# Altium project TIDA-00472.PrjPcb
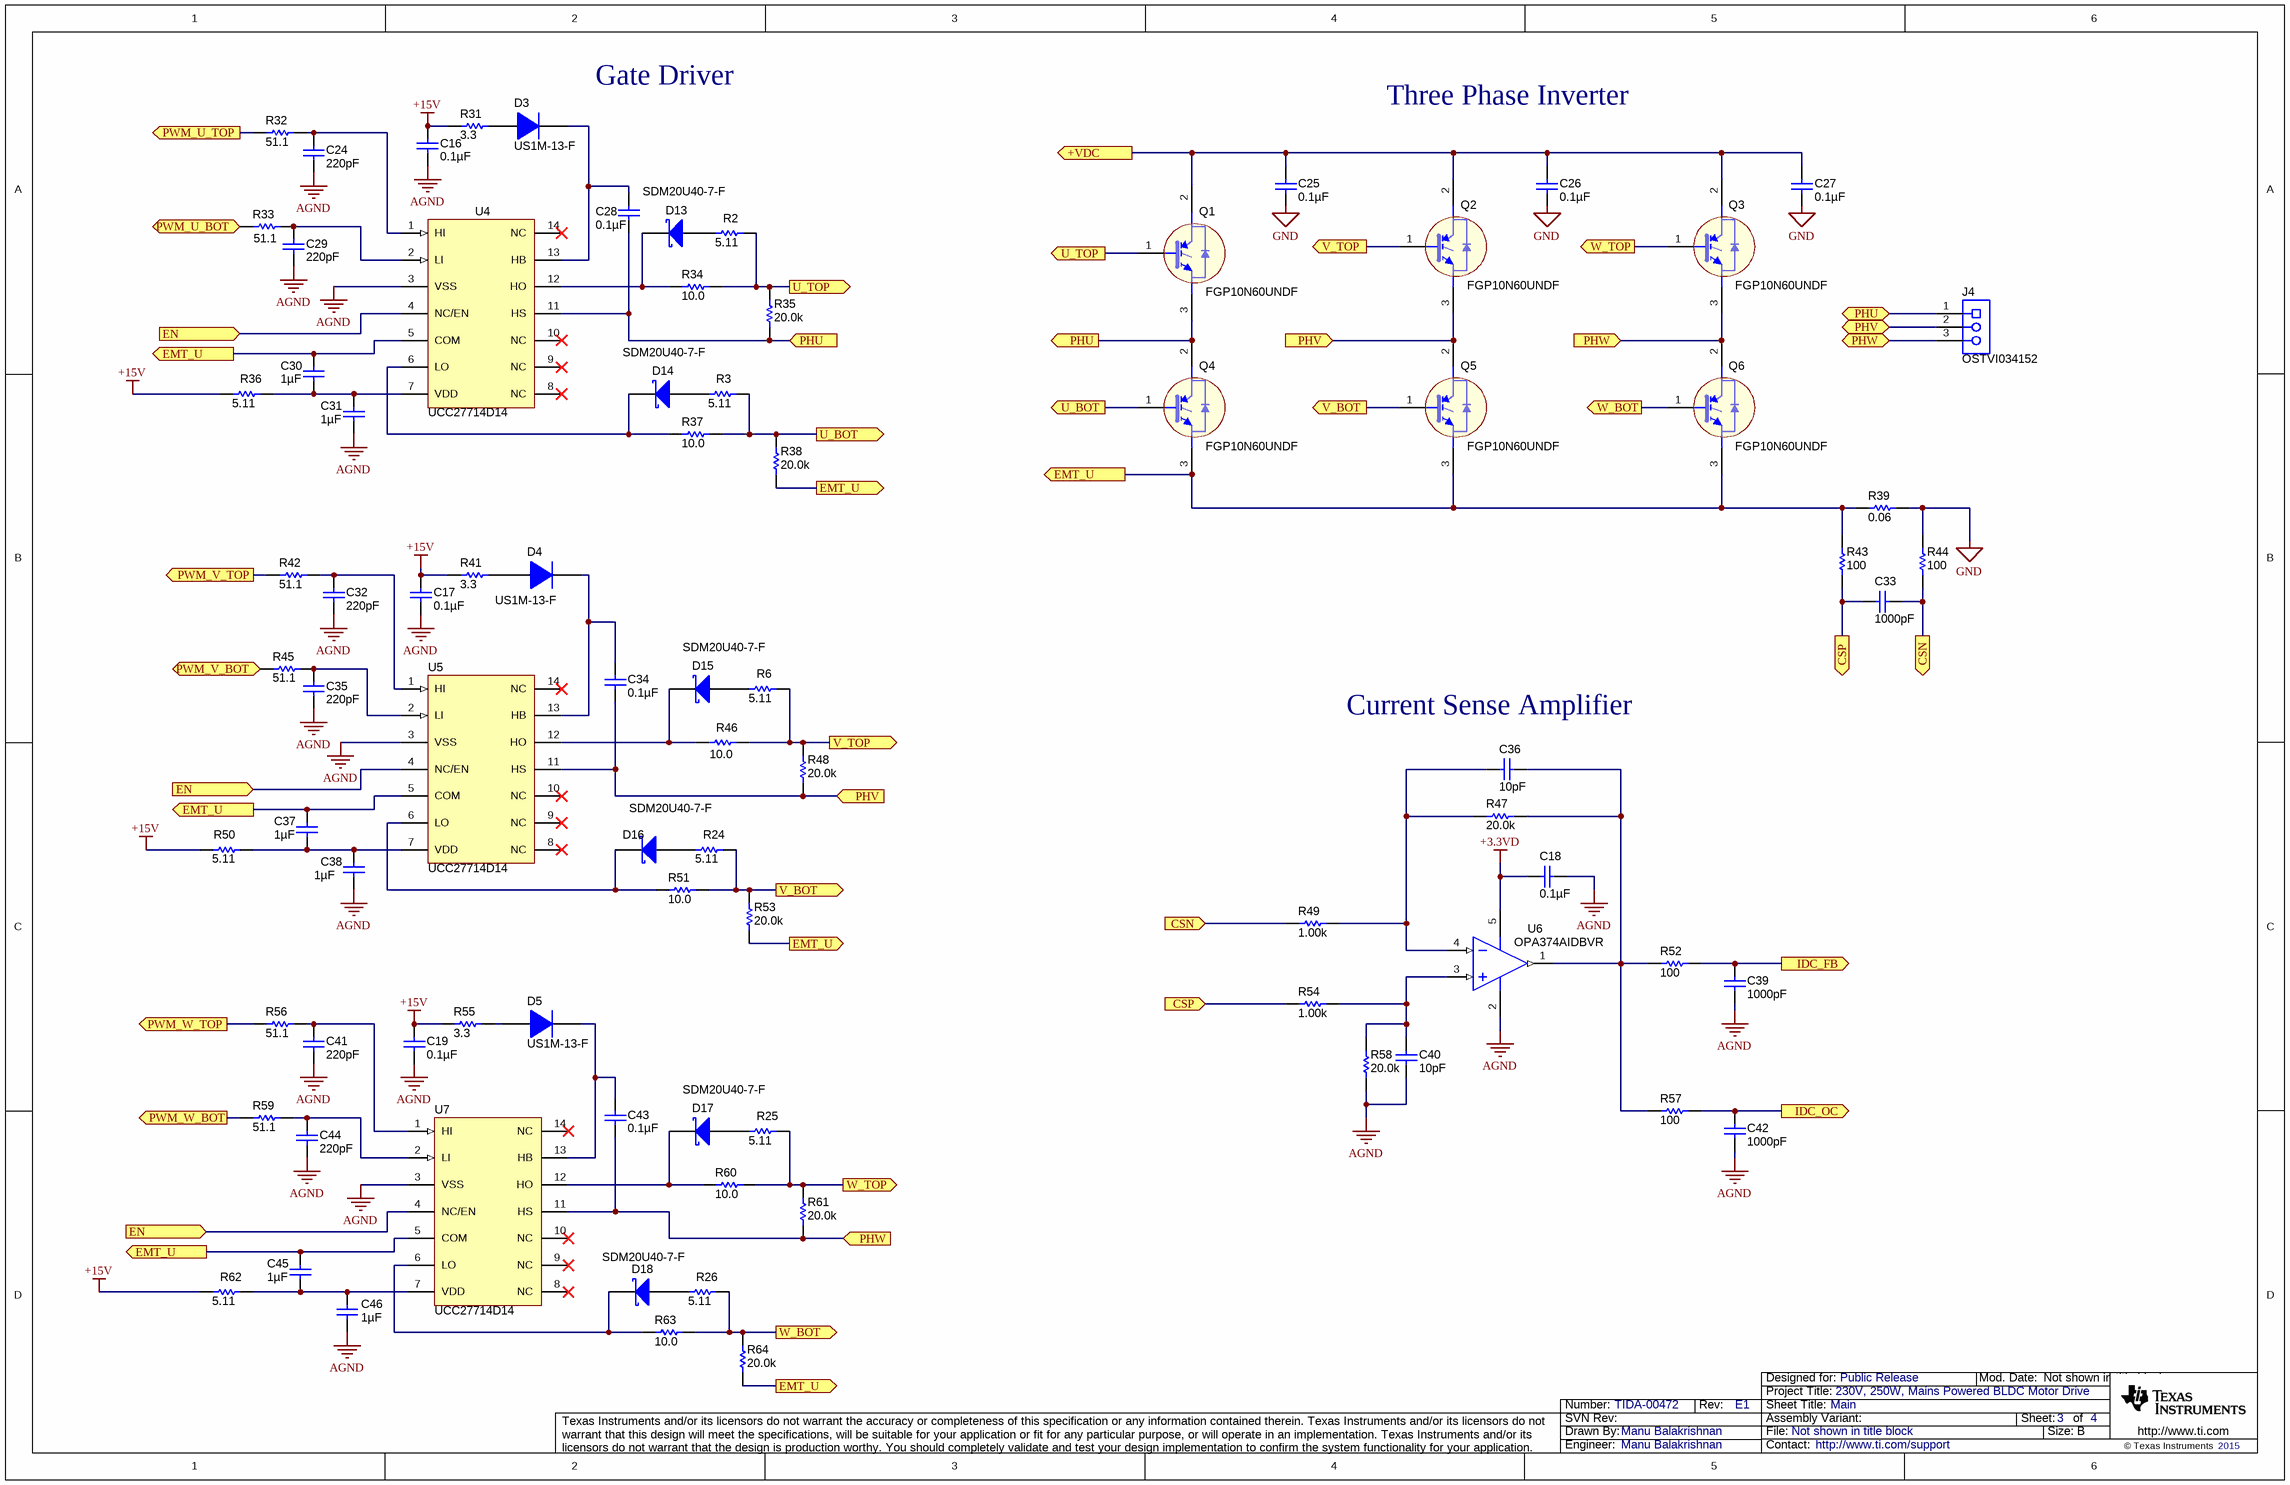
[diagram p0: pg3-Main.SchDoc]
CopyrightYear: 2015; PCB_Layout: Avinash N; PCB_Rev: E1; PRJ_Customer: Public Release; PRJ_Engineer: Manu Balakrishnan; PRJ_Number: TIDA-00472; PRJ_Title: 230V, 250W, Mains Powered BLDC Motor Drive; SCH_Rev: E1; TechSupport: http://www.ti.com/support
4 sheets, 187 parts. Net scope: flat (ports and power ports of the same name join across sheets).
Board file: TIDA-00472.PcbDoc
Sheets:
  pg3-Main.SchDoc
  Pg4-Hardware.SchDoc
  Pg1-Cover_1.SchDoc
  Pg2-Main_1.SchDoc

## Sheet pg3-Main.SchDoc: Main
size 431 x 279 mm; Date: Not shown in title block; ApprovedBy: Not shown in title block; CheckedBy: Not shown in title block; Author: Not shown in title block; CompanyName: Not shown in title block; DrawnBy: Manu Balakrishnan; Engineer: Not shown in title block; Organization: Not shown in title block; Address1: Not shown in title block; Address2: Not shown in title block; Address3: Not shown in title block; Address4: Not shown in title block; DocumentNumber: 2; Revision: Use project parameter SCH_Rev; SheetNumber: 3; SheetTotal: 4; PageSetup: Record=PageOptions¦CenterHorizontal=True¦CenterVertical=True¦PrintScale=0.64¦XCorrection=1.00¦YCorrection=1.00¦PrintKind=0¦BorderSize=5000000¦LeftOffset=0¦BottomOffset=0¦Orientation=2¦PaperLength=1000¦PaperWidth=1000¦Scale=100¦PaperSource=15¦PrintQuality=600¦MediaType=1¦DitherType=10¦PrintScaleMode=1¦PaperKind=Letter

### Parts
C16  ValueDisplayed: 0.1µF  [0603]  (hidden comment: 06033C104JAT2A)
C17  ValueDisplayed: 0.1µF  [0603]  (hidden comment: 06033C104JAT2A)
C18  ValueDisplayed: 0.1µF  [0603]  (hidden comment: 0603YC104JAT2A)
C19  ValueDisplayed: 0.1µF  [0603]  (hidden comment: 06033C104JAT2A)
C24  ValueDisplayed: 220pF  [0603]  (hidden comment: 06035A221FAT2A)
C25  ValueDisplayed: 0.1µF  [1812]  (hidden comment: C1812V104KDRACTU)
C26  ValueDisplayed: 0.1µF  [1812]  (hidden comment: C1812V104KDRACTU)
C27  ValueDisplayed: 0.1µF  [1812]  (hidden comment: C1812V104KDRACTU)
C28  ValueDisplayed: 0.1µF  [0805_HV]  (hidden comment: GRM21BR71E104KA01L)
C29  ValueDisplayed: 220pF  [0603]  (hidden comment: 06035A221FAT2A)
C30  ValueDisplayed: 1µF  [0805_HV]  (hidden comment: GRM21BR71E105KA99L)
C31  ValueDisplayed: 1µF  [0805_HV]  (hidden comment: GRM21BR71E105KA99L)
C32  ValueDisplayed: 220pF  [0603]  (hidden comment: 06035A221FAT2A)
C33  ValueDisplayed: 1000pF  [0603]  (hidden comment: GRM188R61H102KA01D)
C34  ValueDisplayed: 0.1µF  [0805_HV]  (hidden comment: GRM21BR71E104KA01L)
C35  ValueDisplayed: 220pF  [0603]  (hidden comment: 06035A221FAT2A)
C36  ValueDisplayed: 10pF  [0603]  (hidden comment: 06035A100JAT2A)
C37  ValueDisplayed: 1µF  [0805_HV]  (hidden comment: GRM21BR71E105KA99L)
C38  ValueDisplayed: 1µF  [0805_HV]  (hidden comment: GRM21BR71E105KA99L)
C39  ValueDisplayed: 1000pF  [0603]  (hidden comment: GRM188R61H102KA01D)
C40  ValueDisplayed: 10pF  [0603]  (hidden comment: 06035A100JAT2A)
C41  ValueDisplayed: 220pF  [0603]  (hidden comment: 06035A221FAT2A)
C42  ValueDisplayed: 1000pF  [0603]  (hidden comment: GRM188R61H102KA01D)
C43  ValueDisplayed: 0.1µF  [0805_HV]  (hidden comment: GRM21BR71E104KA01L)
C44  ValueDisplayed: 220pF  [0603]  (hidden comment: 06035A221FAT2A)
C45  ValueDisplayed: 1µF  [0805_HV]  (hidden comment: GRM21BR71E105KA99L)
C46  ValueDisplayed: 1µF  [0805_HV]  (hidden comment: GRM21BR71E105KA99L)
D3  US1M-13-F  [SMA]
D4  US1M-13-F  [SMA]
D5  US1M-13-F  [SMA]
D13  SDM20U40-7-F  [SOD-523]
D14  SDM20U40-7-F  [SOD-523]
D15  SDM20U40-7-F  [SOD-523]
D16  SDM20U40-7-F  [SOD-523]
D17  SDM20U40-7-F  [SOD-523]
D18  SDM20U40-7-F  [SOD-523]
J4  OSTVI034152  [ONSHORE_OSTVI034152]
Q1  FGP10N60UNDF  [TO-220AB]
Q2  FGP10N60UNDF  [TO-220AB]
Q3  FGP10N60UNDF  [TO-220AB]
Q4  FGP10N60UNDF  [TO-220AB]
Q5  FGP10N60UNDF  [TO-220AB]
Q6  FGP10N60UNDF  [TO-220AB]
R2  ValueDisplayed: 5.11  [0603]  (hidden comment: RC0603FR-075R11L)
R3  ValueDisplayed: 5.11  [0603]  (hidden comment: RC0603FR-075R11L)
R6  ValueDisplayed: 5.11  [0603]  (hidden comment: RC0603FR-075R11L)
R24  ValueDisplayed: 5.11  [0603]  (hidden comment: RC0603FR-075R11L)
R25  ValueDisplayed: 5.11  [0603]  (hidden comment: RC0603FR-075R11L)
R26  ValueDisplayed: 5.11  [0603]  (hidden comment: RC0603FR-075R11L)
R31  ValueDisplayed: 3.3  [0603]  (hidden comment: CRCW06033R30JNEA)
R32  ValueDisplayed: 51.1  [0603]  (hidden comment: CRCW060351R1FKEA)
R33  ValueDisplayed: 51.1  [0603]  (hidden comment: CRCW060351R1FKEA)
R34  ValueDisplayed: 10.0  [0603]  (hidden comment: CRCW060310R0FKEAHP)
R35  value 20.0k  [0603]  (hidden comment: CRCW060320K0FKEA)
R36  ValueDisplayed: 5.11  [0603]  (hidden comment: RC0603FR-075R11L)
R37  ValueDisplayed: 10.0  [0603]  (hidden comment: CRCW060310R0FKEAHP)
R38  value 20.0k  [0603]  (hidden comment: CRCW060320K0FKEA)
R39  ValueDisplayed: 0.06  [2512]  (hidden comment: PE2512FKE7W0R06L)
R41  ValueDisplayed: 3.3  [0603]  (hidden comment: CRCW06033R30JNEA)
R42  ValueDisplayed: 51.1  [0603]  (hidden comment: CRCW060351R1FKEA)
R43  ValueDisplayed: 100  [0603]  (hidden comment: CRCW0603100RFKEA)
R44  ValueDisplayed: 100  [0603]  (hidden comment: CRCW0603100RFKEA)
R45  ValueDisplayed: 51.1  [0603]  (hidden comment: CRCW060351R1FKEA)
R46  ValueDisplayed: 10.0  [0603]  (hidden comment: CRCW060310R0FKEAHP)
R47  ValueDisplayed: 20.0k  [0603]  (hidden comment: RG1608P-203-B-T5)
R48  value 20.0k  [0603]  (hidden comment: CRCW060320K0FKEA)
R49  ValueDisplayed: 1.00k  [0603]  (hidden comment: CRCW06031K00FKEA)
R50  ValueDisplayed: 5.11  [0603]  (hidden comment: RC0603FR-075R11L)
R51  ValueDisplayed: 10.0  [0603]  (hidden comment: CRCW060310R0FKEAHP)
R52  ValueDisplayed: 100  [0603]  (hidden comment: CRCW0603100RFKEA)
R53  value 20.0k  [0603]  (hidden comment: CRCW060320K0FKEA)
R54  ValueDisplayed: 1.00k  [0603]  (hidden comment: CRCW06031K00FKEA)
R55  ValueDisplayed: 3.3  [0603]  (hidden comment: CRCW06033R30JNEA)
R56  ValueDisplayed: 51.1  [0603]  (hidden comment: CRCW060351R1FKEA)
R57  ValueDisplayed: 100  [0603]  (hidden comment: CRCW0603100RFKEA)
R58  ValueDisplayed: 20.0k  [0603]  (hidden comment: RG1608P-203-B-T5)
R59  ValueDisplayed: 51.1  [0603]  (hidden comment: CRCW060351R1FKEA)
R60  ValueDisplayed: 10.0  [0603]  (hidden comment: CRCW060310R0FKEAHP)
R61  value 20.0k  [0603]  (hidden comment: CRCW060320K0FKEA)
R62  ValueDisplayed: 5.11  [0603]  (hidden comment: RC0603FR-075R11L)
R63  ValueDisplayed: 10.0  [0603]  (hidden comment: CRCW060310R0FKEAHP)
R64  value 20.0k  [0603]  (hidden comment: CRCW060320K0FKEA)
U4  UCC27714D14  [D0014A_N]
U5  UCC27714D14  [D0014A_N]
U6  OPA374AIDBVR  [DBV0005A_N]
U7  UCC27714D14  [D0014A_N]

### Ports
+VDC (out), CSN (in), CSN (out), CSP (in), CSP (out), EMT_U (out), EN (in), IDC_FB (out), IDC_OC (out), PHU (bidir), PHU (in), PHU (out), PHV (bidir), PHV (in), PHW (bidir), PHW (in), PWM_U_BOT (out), PWM_U_TOP (out), PWM_V_BOT (out), PWM_V_TOP (out), PWM_W_BOT (out), PWM_W_TOP (out), U_BOT (out), U_TOP (out), V_BOT (out), V_TOP (out), W_BOT (out), W_TOP (out)

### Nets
+3.3VD: C18.1 U6.5(V+)
+15V: C16.1 C17.1 C19.1 R31.1 R36.1 R41.1 R50.1 R55.1 R62.1
AGND: C16.2 C17.2 C18.2 C19.2 C24.2 C25.2 C26.2 C27.2 C29.2 C31.2 C32.2 C35.2 C38.2 C39.1 C40.2 C41.2 C42.1 C44.2 C46.2 R39.2 R44.2 R58.1 U4.3(VSS) U5.3(VSS) U6.2(V-) U7.3(VSS)  [also labelled GND]
+VDC: C25.1 C26.1 C27.1 Q1.2(C) Q2.2(C) Q3.2(C) ; port +VDC
CSN: C33.2 R44.1 R49.1 ; port CSN
CSP: C33.1 R43.1 R54.1 ; port CSP
EMT_U: C30.1 C37.1 C45.1 Q4.3(E) Q5.3(E) Q6.3(E) R38.1 R39.1 R43.2 R53.1 R64.1 U4.5(COM) U5.5(COM) U7.5(COM) ; port EMT_U
EN: U4.4(NC/EN) U5.4(NC/EN) U7.4(NC/EN) ; port EN
IDC_FB: C39.2 R52.1 ; port IDC_FB
IDC_OC: C42.2 R57.1 ; port IDC_OC
PHU: C28.2 J4.1 Q1.3(E) Q4.2(C) R35.1 U4.11(HS) ; port PHU
PHV: C34.2 J4.2 Q2.3(E) Q5.2(C) R48.1 U5.11(HS) ; port PHV
PHW: C43.2 J4.3 Q3.3(E) Q6.2(C) R61.1 U7.11(HS) ; port PHW
PWM_U_BOT: R33.1 ; port PWM_U_BOT
PWM_U_TOP: R32.1 ; port PWM_U_TOP
PWM_V_BOT: R45.1 ; port PWM_V_BOT
PWM_V_TOP: R42.1 ; port PWM_V_TOP
PWM_W_BOT: R59.1 ; port PWM_W_BOT
PWM_W_TOP: R56.1 ; port PWM_W_TOP
U_BOT: Q4.1(G) R3.2 R37.2 R38.2 ; port U_BOT
U_TOP: Q1.1(G) R2.2 R34.2 R35.2 ; port U_TOP
V_BOT: Q5.1(G) R24.2 R51.2 R53.2 ; port V_BOT
V_TOP: Q2.1(G) R6.2 R46.2 R48.2 ; port V_TOP
W_BOT: Q6.1(G) R26.2 R63.2 R64.2 ; port W_BOT
W_TOP: Q3.1(G) R25.2 R60.2 R61.2 ; port W_TOP
NetC24_1: C24.1 R32.2 U4.1(HI)
NetC28_1: C28.1 D3.1(K) U4.13(HB)
NetC29_1: C29.1 R33.2 U4.2(LI)
NetC30_2: C30.2 C31.1 R36.2 U4.7(VDD)
NetC32_1: C32.1 R42.2 U5.1(HI)
NetC34_1: C34.1 D4.1(K) U5.13(HB)
NetC35_1: C35.1 R45.2 U5.2(LI)
NetC36_1: C36.1 R47.1 R52.2 R57.2 U6.1(OUT)
NetC36_2: C36.2 R47.2 R49.2 U6.4(IN-)
NetC37_2: C37.2 C38.1 R50.2 U5.7(VDD)
NetC40_1: C40.1 R54.2 R58.2 U6.3(IN+)
NetC41_1: C41.1 R56.2 U7.1(HI)
NetC43_1: C43.1 D5.1(K) U7.13(HB)
NetC44_1: C44.1 R59.2 U7.2(LI)
NetC45_2: C45.2 C46.1 R62.2 U7.7(VDD)
NetD3_2: D3.2(A) R31.2
NetD4_2: D4.2(A) R41.2
NetD5_2: D5.2(A) R55.2
NetD13_1: D13.1(K) R34.1 U4.12(HO)
NetD13_2: D13.2(A) R2.1
NetD14_1: D14.1(K) R37.1 U4.6(LO)
NetD14_2: D14.2(A) R3.1
NetD15_1: D15.1(K) R46.1 U5.12(HO)
NetD15_2: D15.2(A) R6.1
NetD16_1: D16.1(K) R51.1 U5.6(LO)
NetD16_2: D16.2(A) R24.1
NetD17_1: D17.1(K) R60.1 U7.12(HO)
NetD17_2: D17.2(A) R25.1
NetD18_1: D18.1(K) R63.1 U7.6(LO)
NetD18_2: D18.2(A) R26.1

Not connected (* = marked no-connect by the designer): U4 8(NC)* 9(NC)* 10(NC)* 14(NC)*; U5 8(NC)* 9(NC)* 10(NC)* 14(NC)*; U7 8(NC)* 9(NC)* 10(NC)* 14(NC)*

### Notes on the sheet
- Gate Driver
- Three Phase Inverter
- (near C36) Current Sense Amplifier

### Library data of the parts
C16 C17 C19 = 06033C104JAT2A: CAP, CERM, 0.1uF, 25V, +/-5%, X7R, 0603; Manufacturer: AVX; Polarized: N; CompType: Capacitor; U/M: EA; Cap_F: 0.0000001; Tolerance_%: 5; ESR_Ohm: 0.05; Value1: 0.05 ohm; VDC_V: 25; TaMin_C: -55; TaMax_C: 125
C18 = 0603YC104JAT2A: CAP, CERM, 0.1uF, 16V, +/-5%, X7R, 0603; Manufacturer: AVX; Polarized: N; CompType: Capacitor; U/M: EA; Cap_F: 0.0000001; Tolerance_%: 5; ESR_Ohm: 0.039; Value1: 0.039 ohm; VDC_V: 16; TaMin_C: -55; TaMax_C: 125
C24 C29 C32 C35 C41 C44 = 06035A221FAT2A: CAP, CERM, 220 pF, 50 V, +/- 1%, C0G/NP0, 0603; Manufacturer: AVX; Polarized: N; CompType: Capacitor; Value: 220pF; U/M: EA; Cap_F: 0.00000000022; Tolerance_%: 1; ESR_ohm: 0.083; Value1: 0.083 ohm; VDC_V: 50; Value2: 50V; TaMin_C: -55; TaMax_C: 125
C25-C27 = VJ1812Y104KXEAT5Z: CAP CER 0.1UF 1KV X7R 1812; Manufacturer: KEMET; Polarized: N; CompType: Capacitor; U/M: EA; Cap_F: 0.0000001; Tolerance_%: 10; Value1: Unknown; VDC_V: 1000; Value2: 1000V; TaMin_C: -55; TaMax_C: 125
C28 C34 C43 = GRM21BR71E104KA01L: CAP, CERM, 0.1 µF, 25 V, +/- 10%, X7R, 0805; Manufacturer: MuRata; Polarized: N; CompType: Capacitor; Value: 0.1uF; U/M: EA; Cap_F: 0.0000001; Tolerance_%: 10; Value1: Unknown; VDC_V: 25; Value2: 25V; TaMin_C: -55; TaMax_C: 125; Cap_Case: 0805
C30 C31 C37 C38 C45 C46 = GRM21BR71E105KA99L: CAP, CERM, 1uF, 25V, +/-10%, X7R, 0805; Manufacturer: MuRata; Polarized: N; CompType: Capacitor; U/M: EA; Cap_F: 0.000001; Tolerance_%: 10; Value1: Unknown; VDC_V: 25; TaMin_C: -55; TaMax_C: 125; Cap_Case: 0805
C33 C39 C42 = GRM188R61H102KA01D: CAP, CERM, 1000 pF, 50 V, +/- 10%, X5R, 0603; Manufacturer: MuRata; Polarized: N; CompType: Capacitor; Value: 1000pF; U/M: EA; Cap_F: 0.000000001; Tolerance_%: 10; Value1: Unknown; VDC_V: 50; Value2: 50V; TaMin_C: -55; TaMax_C: 85
C36 C40 = 06035A100JAT2A: CAP, CERM, 10 pF, 50 V, +/- 5%, C0G/NP0, 0603; Manufacturer: AVX; Polarized: N; CompType: Capacitor; Value: 10pF; U/M: EA; Cap_F: 0.00000000001; Tolerance_%: 5; ESR_ohm: 0.403; Value1: 0.403 ohm; VDC_V: 50; Value2: 50V; TaMin_C: -55; TaMax_C: 125
D3-D5 = US1M-13-F: Diode, Ultrafast, 1000V, 1A, SMA; Manufacturer: Diodes Inc.; U/M: EA; Vf_V: 1.7; Value2: 1.7V; Io_A: 1; Vr_V: 1000; TJmax_C: 150; RJC_CperW: 30
D13-D18 = SDM20U40-7-F: Diode, Schottky, 40 V, 0.25 A, SOD-523; Manufacturer: Diodes Inc.; U/M: EA; Vf_V: 0.55; Value: 40V; Value1: 0.25A; Value2: 0.55V; Io_A: 0.25; Vr_V: 40
J4 = OSTVI034152: TERMINAL BLOCK 7.50MM 3POS PCB, TH; Manufacturer: On-Shore Technology; SymbolCreator: x0199378
Q1-Q6 = STGP14NC60KD: IGBT 600V, 10A 139W TO220-3; Manufacturer: Fairchild Semiconductor; CompType: IGBT, POWER MESH; SymbolCreator: x0199378
R2 R3 R6 R24-R26 R36 R50 R62 = RC0603FR-075R11L: RES, 5.11, 1%, 0.1 W, 0603; Manufacturer: Yageo America; CompType: Resistor; Value: 5.11; Value_Code: 5R11; Tolerance_%: 1; Power_W: 0.1; Value2: 0.1W; VDC_V: 150; TempCo: 200 ppm/C; EIA_Code: E96; U/M: EA
R31 R41 R55 = CRCW06033R30JNEA: RES, 3.3, 5%, 0.1 W, 0603; Manufacturer: Vishay-Dale; CompType: Resistor; Value: 3.3; Value_Code: 3R30; Tolerance_%: 5; Power_W: 0.1; Value2: 0.1W; VDC_V: 75; TempCo: 200 ppm/C; EIA_Code: E24; U/M: EA
R32 R33 R42 R45 R56 R59 = CRCW060351R1FKEA: RES, 51.1, 1%, 0.1 W, 0603; Manufacturer: Vishay-Dale; CompType: Resistor; Value: 51.1; Value_Code: 51R1; Tolerance_%: 1; Power_W: 0.1; Value2: 0.1W; VDC_V: 75; TempCo: 100 ppm/C; EIA_Code: E96; U/M: EA
R34 R37 R46 R51 R60 R63 = CRCW060310R0FKEAHP: RES, 10.0, 1%, 0.25 W, 0603; Manufacturer: Vishay-Dale; CompType: Resistor; Value: 10.0; Res_ohm: 10; Value_Code: 10R0; Tolerance_%: 1; Power_W: 0.25; Value2: 0.25W; VDC_V: 75; TempCo: 100 ppm/C; EIA_Code: E96; U/M: EA
R35 R38 R48 R53 R61 R64 = CRCW060320K0FKEA: RES, 20.0k ohm, 1%, 0.1W, 0603; Manufacturer: Vishay-Dale; CompType: Resistor; Res_ohm: 20000; Value_Code: 20k0; Tolerance_%: 1; Power_W: 0.1; VDC_V: 75; TempCo: 100 ppm/C; EIA_Code: E96; U/M: EA
R39 = CSRN2512FK50L0: RES SMD 0.06 OHM 1% 2W 2512; Manufacturer: YAGEO; CompType: Resistor; Value: 0.06; Value_Code: R050; Tolerance_%: 1; Power_W: 2; TempCo: 200 ppm/C; EIA_Code: E96; U/M: EA
R43 R44 R52 R57 = CRCW0603100RFKEA: RES, 100, 1%, 0.1 W, 0603; Manufacturer: Vishay-Dale; CompType: Resistor; Value: 100; Value_Code: 100R; Tolerance_%: 1; Power_W: 0.1; Value2: 0.1W; VDC_V: 75; TempCo: 100 ppm/C; EIA_Code: E96; U/M: EA
R47 R58 = RG1608P-203-B-T5: RES, 20.0 k, 0.1%, 0.1 W, 0603; Manufacturer: Susumu Co Ltd; CompType: Resistor; Value: 20.0k; Res_ohm: 20000; Value_Code: 20k0; Tolerance_%: 0.1; Value2: 0.1W; VDC_V: 75; TempCo: 25 ppm/C; EIA_Code: E192; U/M: EA
R49 R54 = CRCW06031K00FKEA: RES, 1.00 k, 1%, 0.1 W, 0603; Manufacturer: Vishay-Dale; CompType: Resistor; Value: 1.00k; Res_ohm: 1000; Value_Code: 1k00; Tolerance_%: 1; Power_W: 0.1; Value2: 0.1W; VDC_V: 75; TempCo: 100 ppm/C; EIA_Code: E96; U/M: EA
U4 U5 U7 = UCC27714D14: High-Speed Low-side Gate Driver Device, D0014A; Alternate Manufacturer: None; Manufacturer: Texas Instruments; SymbolCreator: a0411947; CompType: IC; U/M: EA
U6 = OPA374AIDBVR: 6.5 MHz, 585 uA, Rail-to-Rail I/O CMOS Operational Amplifier, 2.3 to 5.5 V, -40 to 125 degC, 5-pin SOT23 (DBV0005A), Green (RoHS & no Sb/Br); Manufacturer: Texas Instruments; Alternate Manufacturer: None; Alternate PartNumber: Equivalent; CMRR(Min)(dB): 80; GBW(Typ)(MHz): 6.5; IIB(Max)(pA): 10; Iq per channel(Max)(mA): 0.75; Number of Channels: 1; Offset Drift(Typ)(uV/C): 3; Packing: LARGE T&R; Rating: Catalog; Slew Rate(Typ)(V/us): 5; Sub Family: High Output Current Amplifier (>=50mA), Low Input Bias Current Amp (<=10pA), Low Supply Voltage Amplifier (<=2.7V), Precision Amplifier; Total Supply Voltage(Max)(+5V is 5, +/-5V is 10): 5.5; Total Supply Voltage(Min)(+5V is 5, +/-5V is 10): 2.3

## Sheet Pg4-Hardware.SchDoc: Main
size 431 x 279 mm; Date: Not shown in title block; ApprovedBy: Not shown in title block; CheckedBy: Not shown in title block; Author: Not shown in title block; CompanyName: Not shown in title block; DrawnBy: Manu Balakrishnan; Engineer: Not shown in title block; Organization: Not shown in title block; Address1: Not shown in title block; Address2: Not shown in title block; Address3: Not shown in title block; Address4: Not shown in title block; DocumentNumber: 2; Revision: E1; SheetNumber: 4; SheetTotal: 4; PageSetup: Record=PageOptions¦CenterHorizontal=True¦CenterVertical=True¦PrintScale=1.00¦XCorrection=1.00¦YCorrection=1.00¦PrintKind=0¦BorderSize=5000000¦LeftOffset=0¦BottomOffset=0¦Orientation=2¦PaperLength=1000¦PaperWidth=1000¦Scale=100¦PaperSource=15¦PrintQuality=600¦MediaType=1¦DitherType=10¦PaperKind=Letter¦PrintScaleMode=1
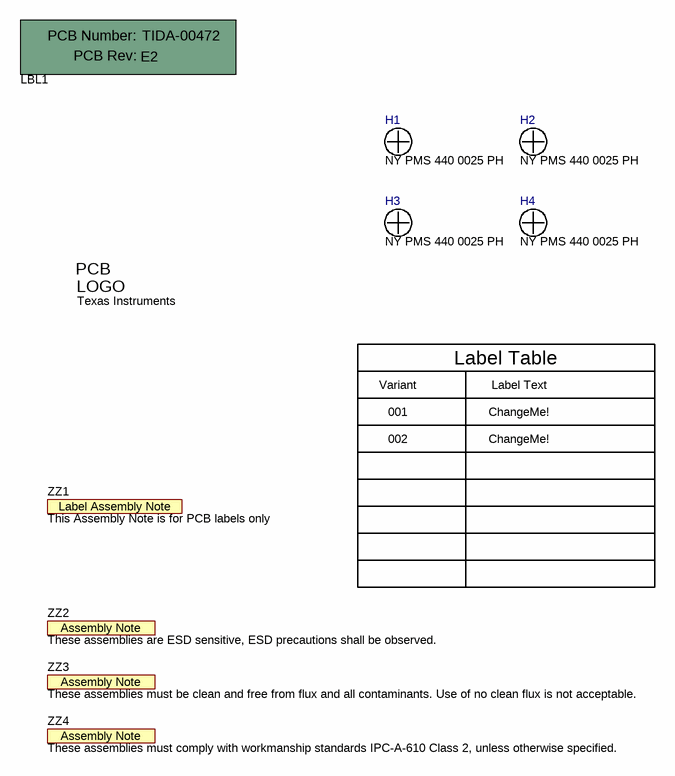
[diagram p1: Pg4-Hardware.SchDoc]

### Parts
H1  NY PMS 440 0025 PH  [NY PMS 440 0025 PH]
H2  NY PMS 440 0025 PH  [NY PMS 440 0025 PH]
H3  NY PMS 440 0025 PH  [NY PMS 440 0025 PH]
H4  NY PMS 440 0025 PH  [NY PMS 440 0025 PH]
LBL1  Printed Circuit Board  [Label_650x200]  (value not drawn)  (mechanical)
Logo2  Texas Instruments  [TI_Stacked_Overlay_Small]  (no BOM)
ZZ1  This Assembly Note is for PCB labels only  [AssemblyNoteLabel]  (no BOM)
ZZ2  These assemblies are ESD sensitive, ESD precautions shall be observed.  [AssemblyNote]  (no BOM)
ZZ3  These assemblies must be clean and free from flux and all contaminants. Use of no clean flux is not acceptable.  [AssemblyNote]  (no BOM)
ZZ4  These assemblies must comply with workmanship standards IPC-A-610 Class 2, unless otherwise specified.  [AssemblyNote]  (no BOM)

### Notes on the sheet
- Variant
- 001
- Label Table
- Label Text
- ChangeMe!
- 002

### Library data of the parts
H1-H4 = NY PMS 440 0025 PH: MACHINE SCREW PAN SLOTTED M3; Manufacturer: Keystone Electronics; PartNumber: 29344; CompType: Hardware; SymbolCreator: codlsc; U/M: EA
LBL1 = PCB: Manufacturer: Any; PartNumber: TIDA-00472; SymbolCreator: a0412235
Logo2 = TI_Logo: Texas Instrument Corporate Signature; SymbolCreator: codlsc
ZZ1 = AssemblyNoteLabel: SymbolCreator: a0412235
ZZ2-ZZ4 = AssemblyNote: SymbolCreator: codlsc

## Sheet Pg1-Cover_1.SchDoc
size 431 x 279 mm; Date: Not shown in title block; ApprovedBy: Not shown in title block; CheckedBy: Not shown in title block; Author: Not shown in title block; CompanyName: Not shown in title block; Engineer: Not shown in title block; Organization: Not shown in title block; Address1: Not shown in title block; Address2: Not shown in title block; Address3: Not shown in title block; Address4: Not shown in title block; DocumentNumber: 1; Revision: Use project parameter SCH_Rev; SheetNumber: 1; SheetTotal: 4; PageSetup: Record=PageOptions¦CenterHorizontal=True¦CenterVertical=True¦PrintScale=1.00¦XCorrection=1.00¦YCorrection=1.00¦PrintKind=0¦BorderSize=5000000¦LeftOffset=0¦BottomOffset=0¦Orientation=2¦PaperLength=1000¦PaperWidth=1000¦Scale=100¦PaperSource=15¦PrintQuality=600¦MediaType=1¦DitherType=10¦PaperKind=Letter¦PrintScaleMode=1
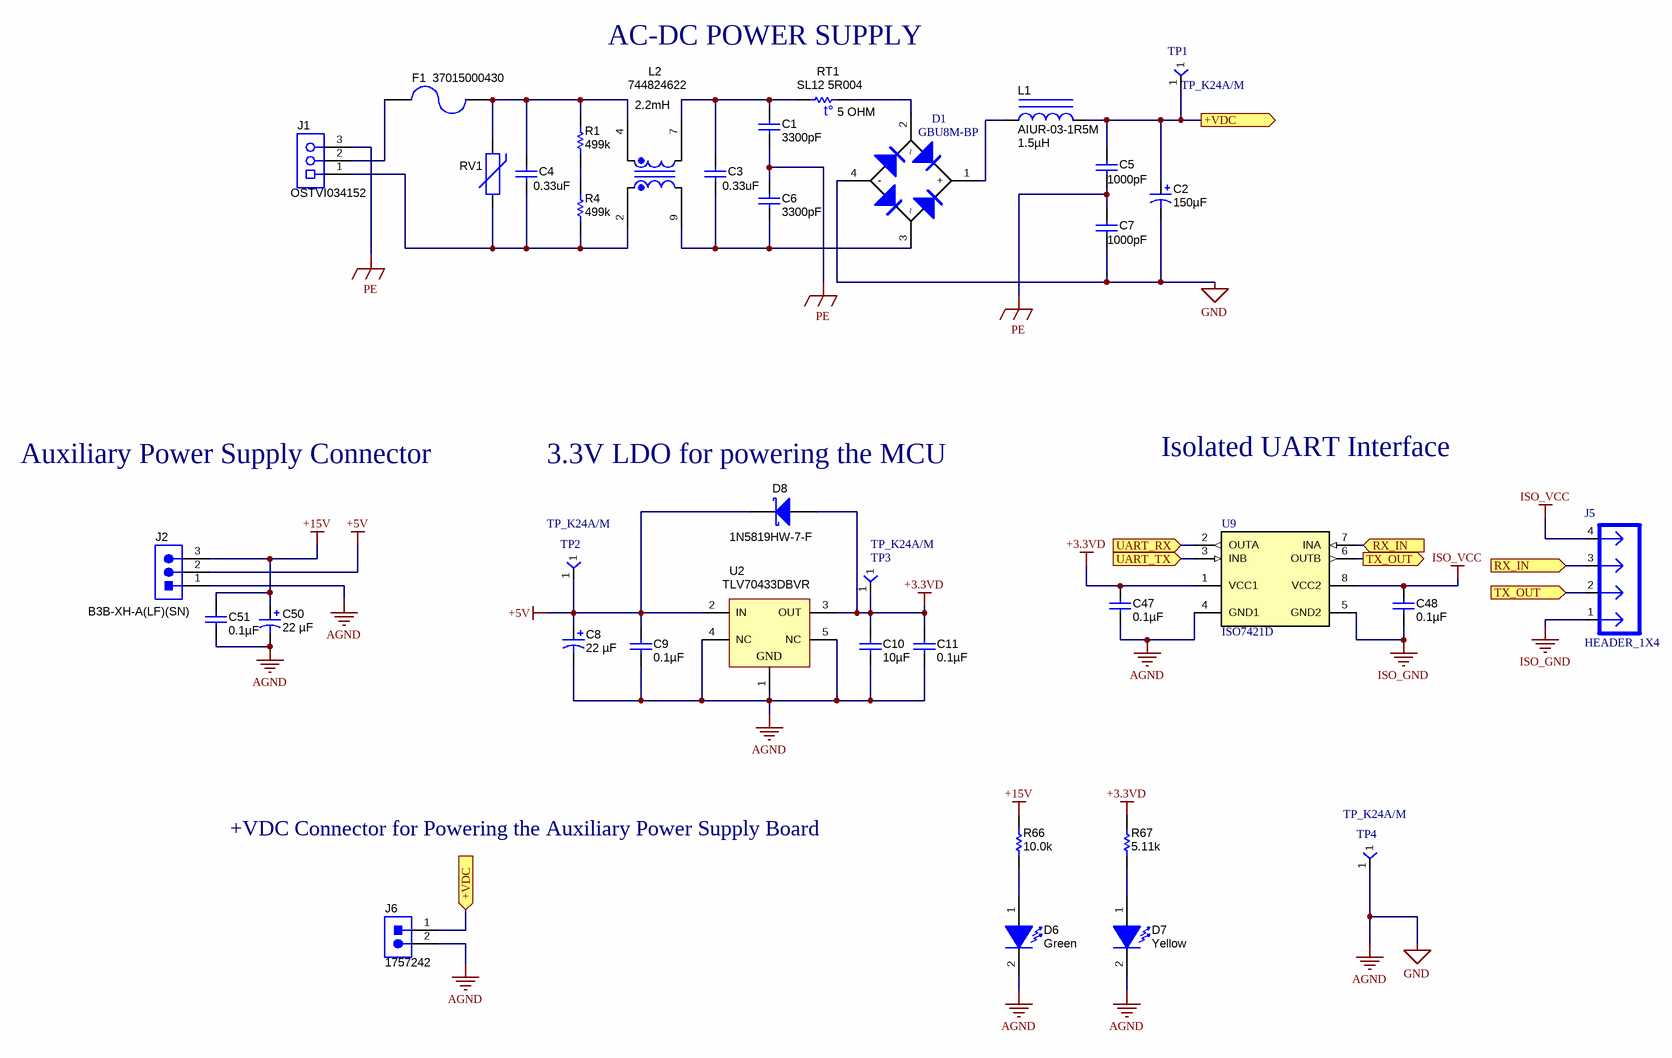
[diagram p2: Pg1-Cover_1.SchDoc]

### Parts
C1  ValueDisplayed: 3300pF  [VY2_1250x500x1650]  (hidden comment: VY2332M41Y5US63V7)
C2  ValueDisplayed: 150µF  [CAPPR10-22x45]  (hidden comment: 400MXK150MEFCSN22X25)
C3  value 0.33uF  [B32922_12mm]  (hidden comment: B32922C3334M189)
C4  value 0.33uF  [B32922_12mm]  (hidden comment: B32922C3334M189)
C5  ValueDisplayed: 1000pF  [CAPRD750W60D1050H1450]  (hidden comment: C901U102MZWDBA7317)
C6  ValueDisplayed: 3300pF  [VY2_1250x500x1650]  (hidden comment: VY2332M41Y5US63V7)
C7  ValueDisplayed: 1000pF  [CAPRD750W60D1050H1450]  (hidden comment: C901U102MZWDBA7317)
C8  ValueDisplayed: 22 µF  [RZ_500x900]  (hidden comment: URZ1E220MDD1TD)
C9  ValueDisplayed: 0.1µF  [0603]  (hidden comment: 06033C104JAT2A)
C10  ValueDisplayed: 10µF  [0805_HV]  (hidden comment: 0805YD106MAT2A)
C11  ValueDisplayed: 0.1µF  [0603]  (hidden comment: 0603YC104JAT2A)
C47  ValueDisplayed: 0.1µF  [0603]  (hidden comment: 06033C104JAT2A)
C48  ValueDisplayed: 0.1µF  [0603]  (hidden comment: 06033C104JAT2A)
C50  ValueDisplayed: 22 µF  [RZ_500x900]  (hidden comment: URZ1E220MDD1TD)
C51  ValueDisplayed: 0.1µF  [0603]  (hidden comment: 06033C104JAT2A)
D1  GBU8M-BP  [GBU]
D6  value Green  [1105W_Red]  (hidden comment: HPG1105W-TR)
D7  value Yellow  [1105W_Red]  (hidden comment: HAY1105W-TR)
D8  1N5819HW-7-F  [SOD-123]
F1  37015000430  [FUSE_37321000430]
J1  OSTVI034152  [ONSHORE_OSTVI034152]
J2  B3B-XH-A(LF)(SN)  [Mill-Max_800-10-003-10-001000]
J5  HEADER_1X4  [Mill-Max_800-10-004-10-001000]
J6  1757242  [PHOENIX_1786404]
L1  AIUR-03-1R5M  ValueDisplayed: 1.5µH  [IND_1300R]
L2  744824622  ValueDisplayed: 2.2mH  [IND_WE-CMB_L]
R1  value 499k  [1206]  (hidden comment: CRCW1206499KFKEA)
R4  value 499k  [1206]  (hidden comment: CRCW1206499KFKEA)
R66  ValueDisplayed: 10.0k  [0603]  (hidden comment: CRCW060310K0FKEA)
R67  ValueDisplayed: 5.11k  [0603]  (hidden comment: CRCW06035K11FKEA)
RT1  SL12 5R004  value 5 OHM  [AMETHERM_SL12XXXXX]
RV1  S10K275E2  [VAR_S10K275E2]  (value not drawn)
TP1  TP_K24A/M  [HOLE-70X43]
TP2  TP_K24A/M  [HOLE-70X43]
TP3  TP_K24A/M  [HOLE-70X43]
TP4  TP_K24A/M  [HOLE-70X43]
U2  TLV70433DBVR  [DBV0005A_N]
U9  ISO7421D  [D0008A_N]

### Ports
+VDC (in), +VDC (out), RX_IN (in), TX_OUT (in), TX_OUT (out), UART_RX (in), UART_TX (in)

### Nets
+3.3VD: C10.1 C11.1 C47.1 D8.2(A) R67.2 TP3.1 U2.3(OUT) U9.1(VCC1)
+5V: C8.1(+) C9.1 D8.1(K) J2.2 TP2.1 U2.2(IN)
+15V: C50.1(+) C51.1 J2.3 R66.1
AGND: C2.2(-) C7.2 C8.2(-) C9.2 C10.2 C11.2 C47.2 C50.2(-) C51.2 D1.4(-) D6.2(K) D7.2(K) J2.1 J6.2 TP4.1 U2.1(GND) U2.4(NC) U2.5(NC) U9.4(GND1)  [also labelled GND]
ISO_GND: C48.2 J5.1 U9.5(GND2)
ISO_VCC: C48.1 J5.4 U9.8(VCC2)
PE: C1.1 C5.2 C6.2 C7.1 J1.3
+VDC: C2.1(+) C5.1 J6.1 L1.2 TP1.1 ; port +VDC
RX_IN: J5.3 U9.7(INA) ; port RX_IN
TX_OUT: J5.2 U9.6(OUTB) ; port TX_OUT
UART_RX: U9.2(OUTA) ; port UART_RX
UART_TX: U9.3(INB) ; port UART_TX
NetC1_2: C1.2 C3.1 L2.7 RT1.1
NetC3_2: C3.2 C6.1 D1.3 L2.9
NetC4_1: C4.1 F1.1 L2.4 R1.2 RV1.2
NetC4_2: C4.2 J1.1 L2.2 R4.1 RV1.1
NetD1_1: D1.1(+) L1.1
NetD1_2: D1.2 RT1.2
NetD6_1: D6.1(A) R66.2
NetD7_1: D7.1(A) R67.1
NetF1_2: F1.2 J1.2
NetR1_1: R1.1 R4.2

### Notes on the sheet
- AC-DC POWER SUPPLY
- Auxiliary Power Supply Connector
- (near D8) 3.3V LDO for powering the MCU
- Isolated UART Interface
- +VDC Connector for Powering the Auxiliary Power Supply Board

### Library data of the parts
C1 C6 = VY2472M49Y5US63V7: CAP CER 3300PF 440VAC 20% RADIAL; Manufacturer: Vishay-Bccomponents; Polarized: N; CompType: Capacitor; U/M: EA; Cap_F: 0.0000000047; Tolerance_%: 20; Value1: Unknown; VDC_V: 440; Value2: 440V; TempCo: Y5U; TaMin_C: -40; TaMax_C: 125; Cap_Case: 12.5x5x16.5
C2 = EET-ED2G181BA: CAP ALUM 150UF 20% 400V SNAP; Manufacturer: Rubycon; Polarized: Y; CompType: Capacitor; U/M: EA; Cap_F: 0.00018; Tolerance_%: 20; Value1: 0.737 ohm; VDC_V: 400; ESR_ohm: 0.737; IRMS_A: 1.03; TaMin_C: -25; TaMax_C: 105; Cap_Case: Radial 10-22x45
C3 C4 = BFC233620154: CAP FILM 0.33UF 630VDC RADIAL; Manufacturer: EPCOS(TDK); CompType: Film Capacitor; SymbolCreator: x0199378
C5 C7 = CS11-E2GA222MYNS: CAP CER 1000PF 440VAC Y5U RADIAL; Manufacturer: KEMET; Polarized: N; CompType: Capacitor; U/M: EA; Cap_F: 0.0000000022; Tolerance_%: 20; Value1: Unknown; Value2: 440V; TempCo: E; TaMin_C: -25; TaMax_C: 105; Cap_Case: Disc, 10.5x7mm
C8 C50 = URZ1E220MDD1TD: CAP, AL, 22uF, 25V, +/-20%, TH; Manufacturer: Nichicon; Polarized: Y; CompType: Capacitor; U/M: EA; Cap_F: 0.000022; Tolerance_%: 20; Value1: Unknown; VDC_V: 25; IRMS_A: 0.055; TaMin_C: -55; TaMax_C: 105; Cap_Case: 5x9mm
C9 C47 C48 C51 = 06033C104JAT2A: as C16 on sheet pg3-Main
C10 = 0805YD106MAT2A: CAP, CERM, 10uF, 16V, +/-20%, X5R, 0805; Manufacturer: AVX; Polarized: N; CompType: Capacitor; U/M: EA; Cap_F: 0.00001; Tolerance_%: 20; Value1: Unknown; VDC_V: 16; TaMin_C: -55; TaMax_C: 85; Cap_Case: 0805
C11 = 0603YC104JAT2A: as C18 on sheet pg3-Main
D1 = GBJ2506-BP: RECT BRIDGE GPP 8A 1000V GBU; Manufacturer: Micro Commercial Co; CompType: Bridge Rectifier; SymbolCreator: x0199378
D6 = HBR1105W-TR: LED GREEN CLEAR 1206 SMD; Manufacturer: Stanley Electric Co., LTD; Vf_V: 1.7; Value2: 1.7V; Io_A: 0.02; Value1: W; Color: red; U/M: EA
D7 = HBR1105W-TR: LED YELLOW CLEAR 1206 SMD; Manufacturer: Stanley Electric Co., LTD; Vf_V: 1.7; Value2: 1.7V; Io_A: 0.02; Value1: W; Color: red; U/M: EA
D8 = 1N5819HW-7-F: Diode, Schottky, 40 V, 1 A, SOD-123; Manufacturer: Diodes Inc.; U/M: EA; Vf_V: 0.45; Value: 40V; Value1: 1A; Value2: 0.45V; Io_A: 1; Vr_V: 40; TJmax_C: 125
F1 = 0216008.MXESPP: FUSE BOARD MOUNT 5A 250VAC RAD; Manufacturer: Littelfuse Inc; U/M: EA; VDC_V: 250; Irating_A: 5; Rtyp_Ohm: 0.0123; Soldering_Wave_MaxTemp_C: 260
J1 = OSTVI034152: as J4 on sheet pg3-Main
J2 = 800-10-003-10-001000: CONN HEADER XH TOP 3POS 2.5MM; Manufacturer: JST Sales America Inc.; SymbolCreator: a0799628; U/M: EA
J5 = HEADER_1X4: Header, Male 4-pin, 100mil spacing,; Manufacturer: Sullins; PartNumber: PEC04SAAN; area: 44000; Value: PEC04SAAN
J6 = 1757242: Header (Shrouded), 5.08 mm, 2x1, Tin, R/A, TH; Manufacturer: Phoenix Contact; SymbolCreator: a0412235; U/M: EA
L1 = 13R103C: FIXED IND 1.5UH 3.3A 16 MOHM TH; Manufacturer: ABRACON; CompType: Inductor; Value: 10uH; Ind_H: 10.0E-6; Irms: 3.3A @ 30C rise; Isat: 8.5A; DCR_ohm: 0.031; Value1: 0.031 ohm; Material: Ferrite; U/M: EA
L2 = 744824310: CHOKE TORROID 2.2MH 6A VERTICAL; Manufacturer: Wurth Elektronik eiSos; SymbolCreator: a0799628; Ind_H: 10.0E-3; CompType: Coupled Inductor; DCR_ohm: 0.105; Isat: 3; Tolerance_%: 30
R1 R4 = CRCW1206499KFKEA: RES, 499k ohm, 1%, 0.25W, 1206; Manufacturer: Vishay-Dale; CompType: Resistor; Res_ohm: 499000; Tolerance_%: 1; Power_W: 0.25; VDC_V: 200; TempCo: 100 ppm/C; EIA_Code: E96; U/M: EA
R66 = CRCW060310K0FKEA: RES, 10.0 k, 1%, 0.1 W, 0603; Manufacturer: Vishay-Dale; CompType: Resistor; Value: 10.0k; Res_ohm: 10000; Value_Code: 10k0; Tolerance_%: 1; Power_W: 0.1; Value2: 0.1W; VDC_V: 75; TempCo: 100 ppm/C; EIA_Code: E96; U/M: EA
R67 = CRCW06035K11FKEA: RES, 5.11 k, 1%, 0.1 W, 0603; Manufacturer: Vishay-Dale; CompType: Resistor; Value: 5.11k; Res_ohm: 5110; Value_Code: 5k11; Tolerance_%: 1; Power_W: 0.1; Value2: 0.1W; VDC_V: 75; TempCo: 100 ppm/C; EIA_Code: E96; U/M: EA
RT1 = SL155R007: ICL 5 OHM 20% 4A 12MM; Manufacturer: AMETHERM; CompType: ThermistorNTC; SymbolCreator: x0199378
RV1 = S10K275E2: Varistor 275V RMS 10MM Radial, TH; Manufacturer: EPCOS; SymbolCreator: a0412235
TP1-TP4 = TP_K24A/M: Pin, Thru Hole, Tin Plate, for 0.062 PCB's; Manufacturer: Vector; PartNumber: K24A/M; area: 0.001 inch; Value: K24A/M
U2 = TLV70433DBVR: Single Output LDO, 150 mA, Fixed 3.3 V Output, 2.5 to 24 V Input, with Ultra-Low IQ, 5-pin SOT-23 (DBV), -40 to 125 degC, Green (RoHS & no Sb/Br); Manufacturer: Texas Instruments; Alternate Manufacturer: None; Alternate PartNumber: Equivalent; Accuracy(%): 2; Fixed Output Options(V): 3.3; Iout(Max)(A): 0.15; Iq(Typ)(mA): 0.003; SubFamily: Single Channel LDO; Vdo(Typ)(mV): 400; Vin(Max)(V): 24; Vin(Min)(V): 2.5
U9 = ISO7421D: 1 Mbps Dual Channels, 1 / 1, Digital Isolator, 3.3 V / 5 V, -40 to +105 degC, 8-pin SOIC (D), Green (RoHS & no Sb/Br); Manufacturer: Texas Instruments; Alternate PartNumber: Equivalent; Datarate(Mbps): 1; Input Noise Filter: None; Insulation Rating(VRMS): 2500; Prop Delay(Max)(ns): 12; Rating: Catalog; Supply Voltage(s)(V): 3.3, 5; TTL/CMOS Input Threshold: TTL

## Sheet Pg2-Main_1.SchDoc: Main
size 431 x 279 mm; Date: Not shown in title block; ApprovedBy: Not shown in title block; CheckedBy: Not shown in title block; Author: Not shown in title block; CompanyName: Not shown in title block; DrawnBy: Manu Balakrishnan; Engineer: Not shown in title block; Organization: Not shown in title block; Address1: Not shown in title block; Address2: Not shown in title block; Address3: Not shown in title block; Address4: Not shown in title block; DocumentNumber: 2; Revision: Use project parameter SCH_Rev; SheetNumber: 2; SheetTotal: 4; PageSetup: Record=PageOptions¦CenterHorizontal=True¦CenterVertical=True¦PrintScale=1.00¦XCorrection=1.00¦YCorrection=1.00¦PrintKind=0¦BorderSize=5000000¦LeftOffset=0¦BottomOffset=0¦Orientation=2¦PaperLength=1000¦PaperWidth=1000¦Scale=100¦PaperSource=15¦PrintQuality=600¦MediaType=1¦DitherType=10¦PaperKind=Letter¦PrintScaleMode=1
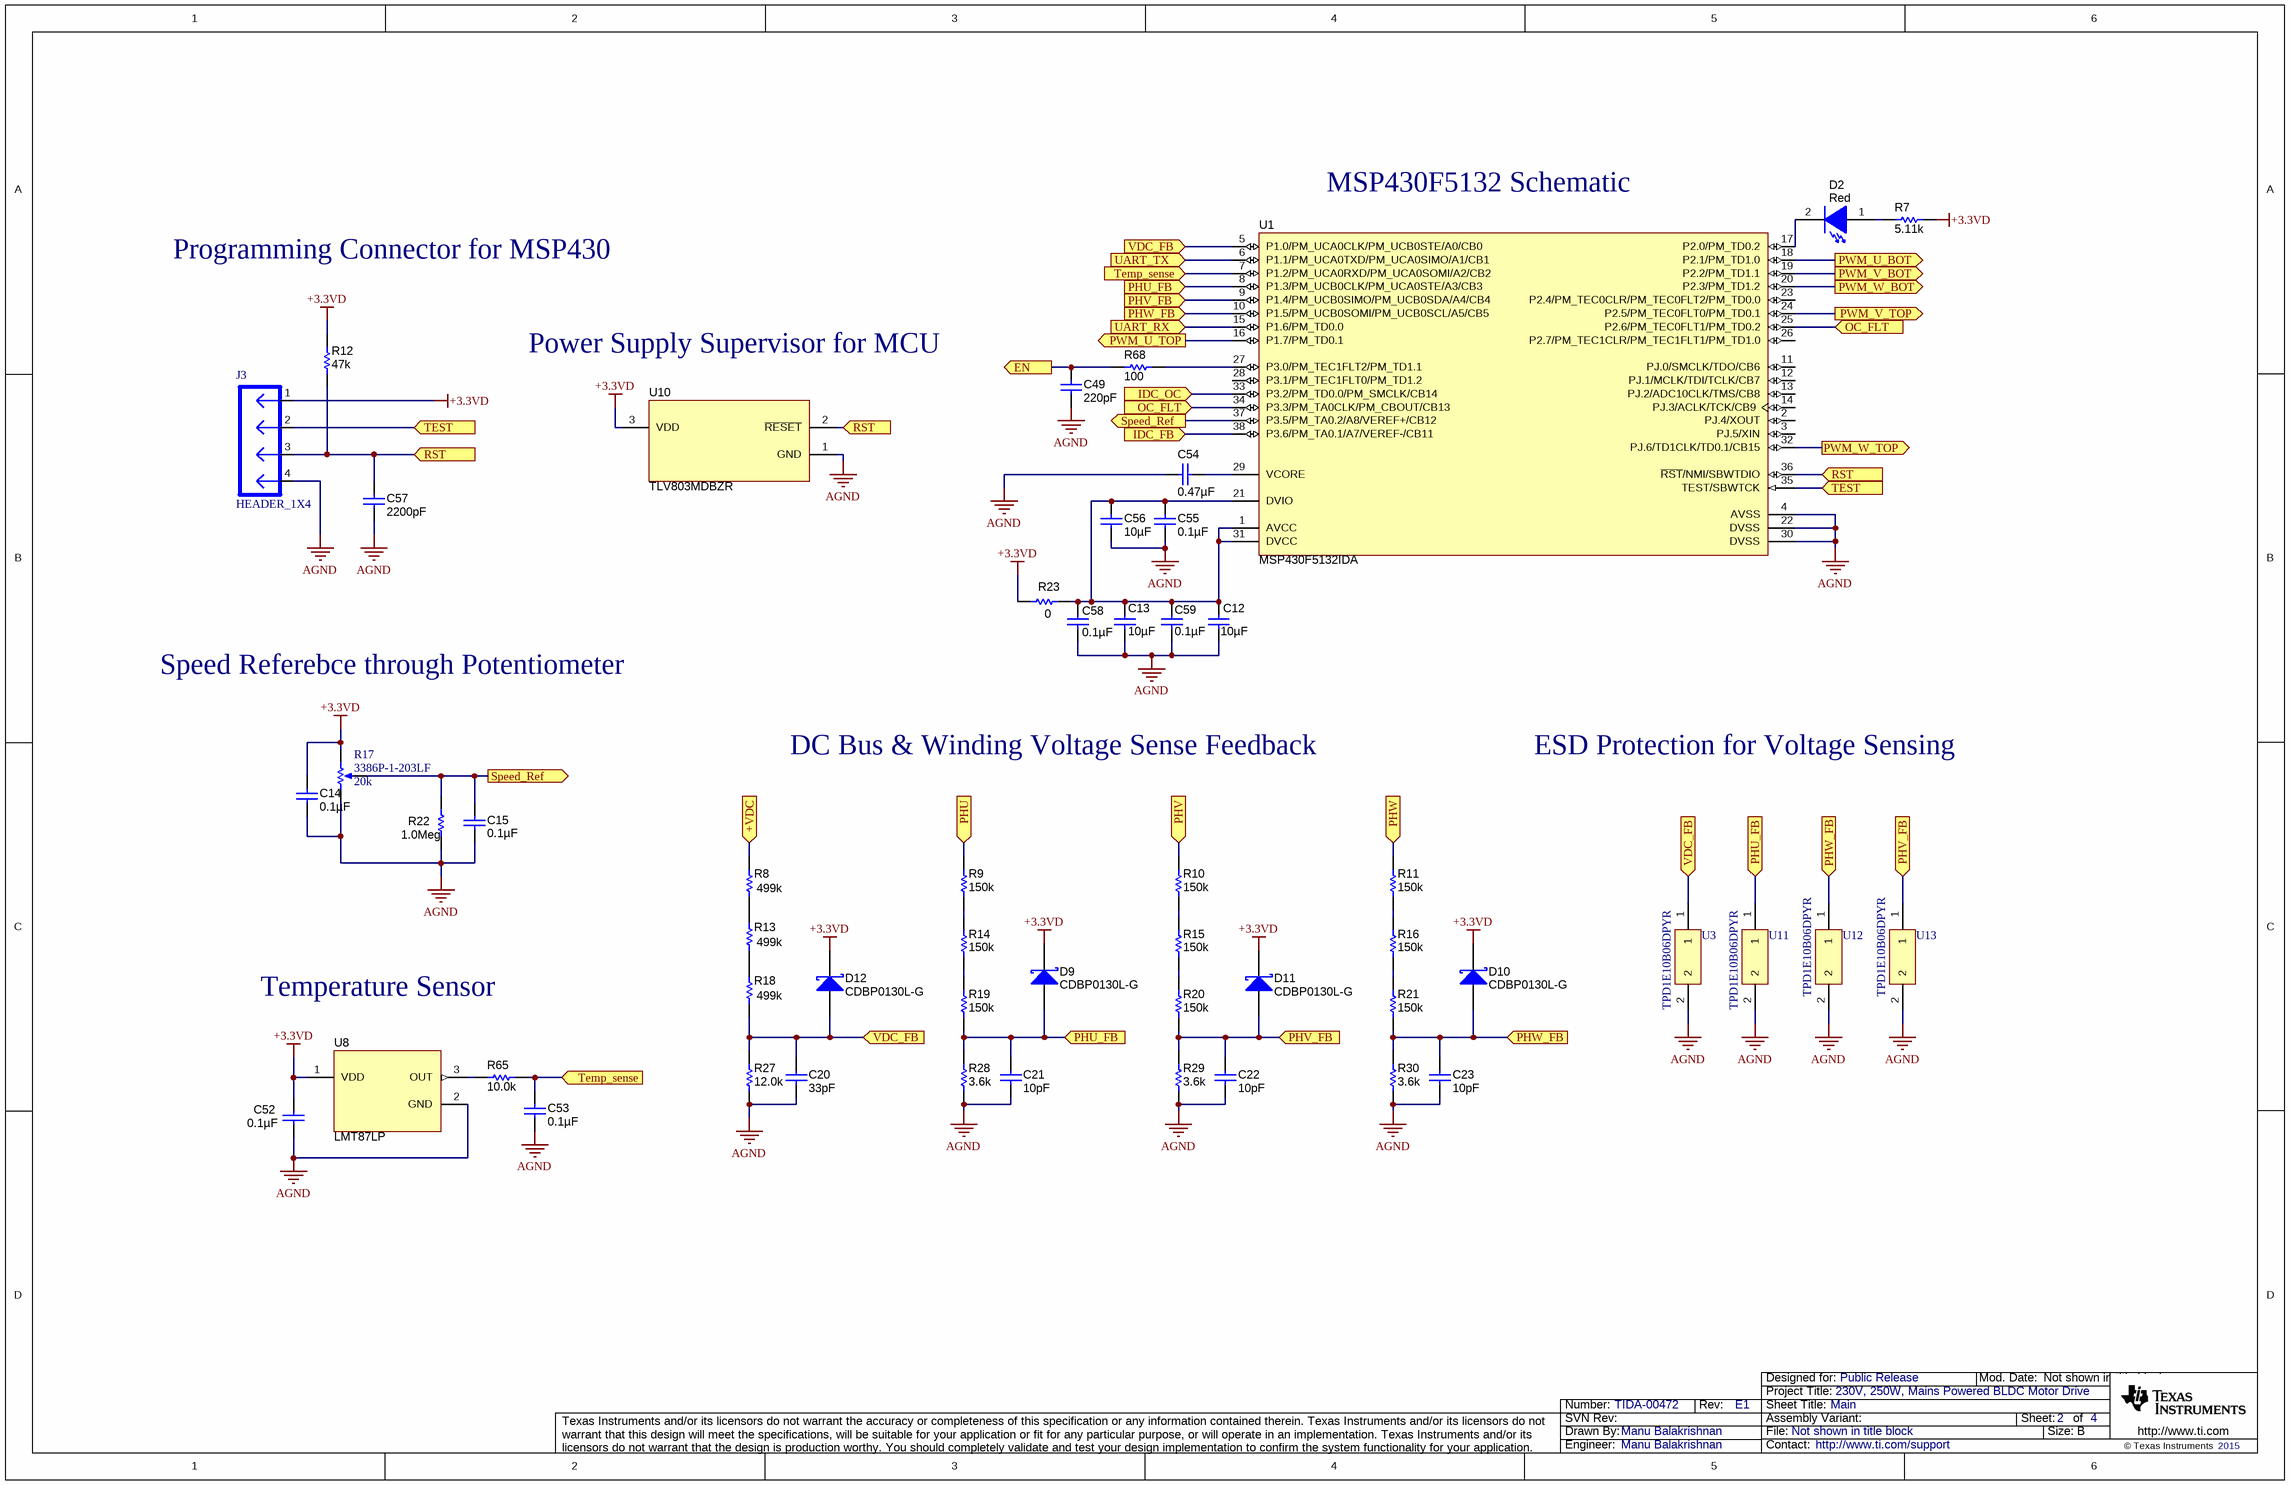
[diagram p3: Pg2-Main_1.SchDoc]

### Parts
C12  ValueDisplayed: 10µF  [0805_HV]  (hidden comment: 0805YD106MAT2A)
C13  ValueDisplayed: 10µF  [0805_HV]  (hidden comment: 0805YD106MAT2A)
C14  ValueDisplayed: 0.1µF  [0603]  (hidden comment: 0603YC104JAT2A)
C15  ValueDisplayed: 0.1µF  [0603]  (hidden comment: 0603YC104JAT2A)
C20  ValueDisplayed: 33pF  [0603]  (hidden comment: 06035A330JAT2A)
C21  ValueDisplayed: 10pF  [0603]  (hidden comment: 06035A100JAT2A)
C22  ValueDisplayed: 10pF  [0603]  (hidden comment: 06035A100JAT2A)
C23  ValueDisplayed: 10pF  [0603]  (hidden comment: 06035A100JAT2A)
C49  ValueDisplayed: 220pF  [0603]  (hidden comment: 06035A221FAT2A)
C52  ValueDisplayed: 0.1µF  [0603]  (hidden comment: 0603YC104JAT2A)
C53  ValueDisplayed: 0.1µF  [0603]  (hidden comment: 0603YC104JAT2A)
C54  ValueDisplayed: 0.47µF  [0805_HV]  (hidden comment: C0805C474K4RACTU)
C55  ValueDisplayed: 0.1µF  [0603]  (hidden comment: 0603YC104JAT2A)
C56  ValueDisplayed: 10µF  [0805_HV]  (hidden comment: 0805YD106MAT2A)
C57  ValueDisplayed: 2200pF  [0603]  (hidden comment: C0603C222K5RAC)
C58  ValueDisplayed: 0.1µF  [0603]  (hidden comment: 0603YC104JAT2A)
C59  ValueDisplayed: 0.1µF  [0603]  (hidden comment: 0603YC104JAT2A)
D2  value Red  [1105W_Red]  (hidden comment: HBR1105W-TR)
D9  CDBP0130L-G  [SOD-723]
D10  CDBP0130L-G  [SOD-723]
D11  CDBP0130L-G  [SOD-723]
D12  CDBP0130L-G  [SOD-723]
J3  HEADER_1X4  [Mill-Max_800-10-004-10-001000]
R7  ValueDisplayed: 5.11k  [0603]  (hidden comment: CRCW06035K11FKEA)
R8  ValueDisplayed: 499k  [1206]  (hidden comment: RC1206FR-07499KL)
R9  value 150k  [1206]  (hidden comment: CRCW1206150KFKEA)
R10  value 150k  [1206]  (hidden comment: CRCW1206150KFKEA)
R11  value 150k  [1206]  (hidden comment: CRCW1206150KFKEA)
R12  value 47k  [0603]  (hidden comment: CRCW060347K0JNEA)
R13  ValueDisplayed: 499k  [1206]  (hidden comment: RC1206FR-07499KL)
R14  value 150k  [1206]  (hidden comment: CRCW1206150KFKEA)
R15  value 150k  [1206]  (hidden comment: CRCW1206150KFKEA)
R16  value 150k  [1206]  (hidden comment: CRCW1206150KFKEA)
R17  3386P-1-203LF  value 20k  [TRIM_3362P]
R18  ValueDisplayed: 499k  [1206]  (hidden comment: RC1206FR-07499KL)
R19  value 150k  [1206]  (hidden comment: CRCW1206150KFKEA)
R20  value 150k  [1206]  (hidden comment: CRCW1206150KFKEA)
R21  value 150k  [1206]  (hidden comment: CRCW1206150KFKEA)
R22  value 1.0Meg  [0603]  (hidden comment: CRCW06031M00JNEA)
R23  ValueDisplayed: 0  [0603]  (hidden comment: RC0603FR-070RL)
R27  ValueDisplayed: 12.0k  [0603]  (hidden comment: RC0603FR-0712KL)
R28  ValueDisplayed: 3.6k  [0603]  (hidden comment: CRCW06033K60JNEA)
R29  ValueDisplayed: 3.6k  [0603]  (hidden comment: CRCW06033K60JNEA)
R30  ValueDisplayed: 3.6k  [0603]  (hidden comment: CRCW06033K60JNEA)
R65  ValueDisplayed: 10.0k  [0603]  (hidden comment: CRCW060310K0FKEA)
R68  ValueDisplayed: 100  [0603]  (hidden comment: CRCW0603100RFKEA)
U1  MSP430F5132IDA  [DA0038A_N]
U3  TPD1E10B06DPYR  [DPY0002A]
U8  LMT87LP  [LPC0003A]
U10  TLV803MDBZR  [DBZ0003A_N]
U11  TPD1E10B06DPYR  [DPY0002A]
U12  TPD1E10B06DPYR  [DPY0002A]
U13  TPD1E10B06DPYR  [DPY0002A]

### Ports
+VDC (in), EN (out), IDC_FB (in), IDC_OC (in), OC_FLT (in), PHU (in), PHU_FB (in), PHV (in), PHV_FB (in), PHW (in), PHW_FB (in), PWM_U_BOT (out), PWM_U_TOP (out), PWM_V_BOT (out), PWM_V_TOP (out), PWM_W_BOT (out), PWM_W_TOP (out), RST (in), Speed_Ref (out), Temp_sense (in), TEST (in), UART_RX (in), UART_TX (in), VDC_FB (in)

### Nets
+3.3VD: C14.1 C52.1 D9.1(K) D10.1(K) D11.1(K) D12.1(K) J3.1 R7.1 R12.2 R17.3(CW) R23.1 U8.1(VDD) U10.3(VDD)
AGND: C12.2 C13.2 C14.2 C15.2 C20.2 C21.2 C22.2 C23.2 C49.2 C52.2 C53.2 C54.2 C55.2 C56.2 C57.2 C58.2 C59.2 J3.4 R17.1(CCW) R22.1 R27.1 R28.1 R29.1 R30.1 U1.4(AVSS) U1.22(DVSS) U1.30(DVSS) U3.2 U8.2(GND) U10.1(GND) U11.2 U12.2 U13.2
+VDC: R8.2 ; port +VDC
EN: C49.1 R68.2 ; port EN
IDC_FB: U1.38(P3.6/PM_TA0.1/A7/VEREF-/CB11) ; port IDC_FB
IDC_OC: U1.33(P3.2/PM_TD0.0/PM_SMCLK/CB14) ; port IDC_OC
OC_FLT: U1.25(P2.6/PM_TEC0FLT1/PM_TD0.2) U1.34(P3.3/PM_TA0CLK/PM_CBOUT/CB13) ; port OC_FLT
PHU: R9.2 ; port PHU
PHU_FB: C21.1 D9.2(A) R19.1 R28.2 U1.8(P1.3/PM_UCB0CLK/PM_UCA0STE/A3/CB3) U11.1 ; port PHU_FB
PHV: R10.2 ; port PHV
PHV_FB: C22.1 D11.2(A) R20.1 R29.2 U1.9(P1.4/PM_UCB0SIMO/PM_UCB0SDA/A4/CB4) U13.1 ; port PHV_FB
PHW: R11.2 ; port PHW
PHW_FB: C23.1 D10.2(A) R21.1 R30.2 U1.10(P1.5/PM_UCB0SOMI/PM_UCB0SCL/A5/CB5) U12.1 ; port PHW_FB
PWM_U_BOT: U1.18(P2.1/PM_TD1.0) ; port PWM_U_BOT
PWM_U_TOP: U1.16(P1.7/PM_TD0.1) ; port PWM_U_TOP
PWM_V_BOT: U1.19(P2.2/PM_TD1.1) ; port PWM_V_BOT
PWM_V_TOP: U1.24(P2.5/PM_TEC0FLT0/PM_TD0.1) ; port PWM_V_TOP
PWM_W_BOT: U1.20(P2.3/PM_TD1.2) ; port PWM_W_BOT
PWM_W_TOP: U1.32(PJ.6/TD1CLK/TD0.1/CB15) ; port PWM_W_TOP
RST: C57.1 J3.3 R12.1 U1.36(~{RST}/NMI/SBWTDIO) U10.2(~{RESET}) ; port RST
Speed_Ref: C15.1 R17.2(WIPER) R22.2 U1.37(P3.5/PM_TA0.2/A8/VEREF+/CB12) ; port Speed_Ref
Temp_sense: C53.1 R65.2 U1.7(P1.2/PM_UCA0RXD/PM_UCA0SOMI/A2/CB2) ; port Temp_sense
TEST: J3.2 U1.35(TEST/SBWTCK) ; port TEST
UART_RX: U1.15(P1.6/PM_TD0.0) ; port UART_RX
UART_TX: U1.6(P1.1/PM_UCA0TXD/PM_UCA0SIMO/A1/CB1) ; port UART_TX
VDC_FB: C20.1 D12.2(A) R18.1 R27.2 U1.5(P1.0/PM_UCA0CLK/PM_UCB0STE/A0/CB0) U3.1 ; port VDC_FB
NetC12_1: C12.1 C13.1 C55.1 C56.1 C58.1 C59.1 R23.2 U1.1(AVCC) U1.21(DVIO) U1.31(DVCC)
NetC54_1: C54.1 U1.29(VCORE)
NetD2_1: D2.1(A) R7.2
NetD2_2: D2.2(K) U1.17(P2.0/PM_TD0.2)
NetR8_1: R8.1 R13.2
NetR9_1: R9.1 R14.2
NetR10_1: R10.1 R15.2
NetR11_1: R11.1 R16.2
NetR13_1: R13.1 R18.2
NetR14_1: R14.1 R19.2
NetR15_1: R15.1 R20.2
NetR16_1: R16.1 R21.2
NetR65_1: R65.1 U8.3(OUT)
NetR68_1: R68.1 U1.27(P3.0/PM_TEC1FLT2/PM_TD1.1)

Not connected (* = marked no-connect by the designer): U1 2(PJ.4/XOUT) 3(PJ.5/XIN) 11(PJ.0/SMCLK/TDO/CB6) 12(PJ.1/MCLK/TDI/TCLK/CB7) 13(PJ.2/ADC10CLK/TMS/CB8) 14(PJ.3/ACLK/TCK/CB9) 23(P2.4/PM_TEC0CLR/PM_TEC0FLT2/PM_TD0.0) 26(P2.7/PM_TEC1CLR/PM_TEC1FLT1/PM_TD1.0) 28(P3.1/PM_TEC1FLT0/PM_TD1.2)

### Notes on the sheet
- (near U1) MSP430F5132 Schematic
- Programming Connector for MSP430
- Power Supply Supervisor for MCU
- Speed Referebce through Potentiometer
- DC Bus & Winding Voltage Sense Feedback
- ESD Protection for Voltage Sensing
- Temperature Sensor

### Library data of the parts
C12 C13 C56 = 0805YD106MAT2A: as C10 on sheet Pg1-Cover_1
C14 C15 C52 C53 = 0603YC104JAT2A: as C18 on sheet pg3-Main
C20 = 06035A330JAT2A: CAP, CERM, 33 pF, 50 V, +/- 5%, C0G/NP0, 0603; Manufacturer: AVX; Polarized: N; CompType: Capacitor; Value: 33pF; U/M: EA; Cap_F: 0.000000000033; Tolerance_%: 5; ESR_ohm: 0.209; Value1: 0.209 ohm; VDC_V: 50; Value2: 50V; TaMin_C: -55; TaMax_C: 125
C21-C23 = 06035A100JAT2A: as C36 on sheet pg3-Main
C49 = 06035A221FAT2A: as C24 on sheet pg3-Main
C54 = C0805C474K4RACTU: CAP, CERM, 0.47 µF, 16 V, +/- 10%, X7R, 0805; Manufacturer: Kemet; Polarized: N; CompType: Capacitor; Value: 0.47uF; U/M: EA; Cap_F: 0.00000047; Tolerance_%: 10; Value1: Unknown; VDC_V: 16; Value2: 16V; TaMin_C: -55; TaMax_C: 125; Cap_Case: 0805
C55 C58 C59 = 0603YC104JAT2A: CAP, CERM, 0.1 µF, 16 V, +/- 5%, X7R, 0603; Manufacturer: AVX; Polarized: N; CompType: Capacitor; Value: 0.1uF; U/M: EA; Cap_F: 0.0000001; Tolerance_%: 5; ESR_ohm: 0.039; Value1: 0.039 ohm; VDC_V: 16; Value2: 16V; TaMin_C: -55; TaMax_C: 125
C57 = C0603C222K5RAC: CAP, CERM, 2200 pF, 50 V, +/- 10%, X7R, 0603; Manufacturer: Kemet; Polarized: N; CompType: Capacitor; Value: 2200pF; U/M: EA; Cap_F: 0.0000000022; Tolerance_%: 10; Value1: Unknown; VDC_V: 50; Value2: 50V; TaMin_C: -55; TaMax_C: 125
D2 = HBR1105W-TR: LED RED CLEAR 1206 SMD; Manufacturer: Stanley Electric Co., LTD; Vf_V: 1.7; Value2: 1.7V; Io_A: 0.02; Value1: W; U/M: EA
D9-D12 = CDBP0130L-G: Diode, Schottky, 30 V, 0.1 A, SOD-723; Manufacturer: Comchip Technology; U/M: EA; Vf_V: 0.35; Value: 30V; Value1: 0.1A; Value2: 0.35V; Io_A: 0.1; Vr_V: 30; TJmax_C: 125
J3 = HEADER_1X4: as J5 on sheet Pg1-Cover_1
R7 = CRCW06035K11FKEA: as R67 on sheet Pg1-Cover_1
R8 R13 R18 = RC1206FR-07499KL: RES, 499 k, 1%, 0.25 W, 1206; Manufacturer: Yageo America; CompType: Resistor; Value: 499k; Res_ohm: 499000; Tolerance_%: 1; Power_W: 0.25; Value2: 0.25W; VDC_V: 200; TempCo: 100 ppm/C; EIA_Code: E96; U/M: EA
R9-R11 R14-R16 R19-R21 = CRCW1206150KFKEA: RES, 150k ohm, 1%, 0.25W, 1206; Manufacturer: Vishay-Dale; CompType: Resistor; Res_ohm: 150000; Tolerance_%: 1; Power_W: 0.25; VDC_V: 200; TempCo: 100 ppm/C; EIA_Code: E96; U/M: EA
R12 = CRCW060347K0JNEA: RES, 47k ohm, 5%, 0.1W, 0603; Manufacturer: Vishay-Dale; CompType: Resistor; Res_ohm: 47000; Value_Code: 47k0; Tolerance_%: 5; Power_W: 0.1; VDC_V: 75; TempCo: 200 ppm/C; EIA_Code: E24; U/M: EA
R17 = 3386P-1-203LF: TRIMMER, 20k ohm, 0.5W, TH; Manufacturer: Bourns; Sim Note: Enter the Resistance value and the set point into parameter fields.; SymbolCreator: a0412235
R22 = CRCW06031M00JNEA: RES, 1.0Meg ohm, 5%, 0.1W, 0603; Manufacturer: Vishay-Dale; CompType: Resistor; Res_ohm: 1000000; Value_Code: 1M00; Tolerance_%: 5; Power_W: 0.1; VDC_V: 75; TempCo: 200 ppm/C; EIA_Code: E24; U/M: EA
R23 = RC0603FR-075R11L: RES SMD 0.0OHM JUMPER 1/10W 0603; Manufacturer: Yageo; CompType: Resistor; Value: 0; Tolerance_%: 1; Value1: 1%; Power_W: 0.1; Value2: 0.1W; VDC_V: 150; TempCo: 200 ppm/C; EIA_Code: E96; U/M: EA
R27 = RC0603FR-0712KL: RES, 12.0 k, 1%, 0.1 W, 0603; Manufacturer: Yageo America; CompType: Resistor; Value: 12.0k; Res_ohm: 12000; Value_Code: 12k0; Tolerance_%: 1; Power_W: 0.1; Value2: 0.1W; VDC_V: 150; TempCo: 200 ppm/C; U/M: EA
R28-R30 = CRCW06033K60JNEA: RES, 3.6 k, 5%, 0.1 W, 0603; Manufacturer: Vishay-Dale; CompType: Resistor; Value: 3.6k; Res_ohm: 3600; Value_Code: 3k60; Tolerance_%: 5; Power_W: 0.1; Value2: 0.1W; VDC_V: 75; TempCo: 200 ppm/C; EIA_Code: E24; U/M: EA
R65 = CRCW060310K0FKEA: as R66 on sheet Pg1-Cover_1
R68 = CRCW0603100RFKEA: as R43 on sheet pg3-Main
U1 = MSP430F5132IDA: 25 MHz Mixed Signal Microcontroller with 8 KB Flash, 1024 B SRAM and 29 GPIOs, -40 to 85 degC, 38-pin SOP (DA), Green (RoHS & no Sb/Br); Alternate Manufacturer: Texas Instruments; Alternate PartNumber: Equivalent; ADC: 10-bit SAR; ADC Channels: 8; Brown Out Reset: Yes; DMA: 3; Frequency(MHz): 25; GPIO: 29; Multiplier: 32x32; Pin/Package: 38TSSOP, 40WQFN; SRAM(B): 1024; SubFamily: 5 Series; USCI_A (UART/LIN/IrDA/SPI): 1
U3 U11-U13 = TPD1E10B06DPYR: ESD in 0402 Package with 10 pF Capacitance and 6 V Breakdown, 1 Channel, -40 to +125 degC, 2-pin X2SON (DPY), Green (RoHS & no Sb/Br); Manufacturer: Texas Instruments; Alternate Manufacturer: None; Alternate PartNumber: Equivalent; Breakdown Voltage(Min)(V): 6; Eco-Plan: TBD; IEC 61000-4-2 Air-Gap(+/- kV): 30; IO Capacitance(Typ)(pF): 10; SubFamily: ESD Solution
U8 = LMT87LPC: Analog Temperature Sensors with Class-AB Output, LPC0003A; Manufacturer: Texas Instruments; SymbolCreator: Altium; CompType: IC; U/M: EA
U10 = TLV803MDBZR: 3-Pin Voltage Supervisors with Active-Low, Open-Drain Reset, DBZ0003A; Alternate PartNumber: TLV803MDBZT; Manufacturer: Texas Instruments; SymbolCreator: Altium; CompType: IC; U/M: EA

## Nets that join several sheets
+3.3VD: pg3-Main (C18.1 U6.5), Pg1-Cover_1 (8 pins), Pg2-Main_1 (13 pins)
+15V: pg3-Main (9 pins), Pg1-Cover_1 (C50.1 C51.1 J2.3 R66.1)
AGND: pg3-Main (26 pins), Pg1-Cover_1 (19 pins), Pg2-Main_1 (33 pins)
+VDC: pg3-Main (6 pins), Pg1-Cover_1 (5 pins), Pg2-Main_1 (R8.2)
EN: pg3-Main (U4.4 U5.4 U7.4), Pg2-Main_1 (C49.1 R68.2)
IDC_FB: pg3-Main (C39.2 R52.1), Pg2-Main_1 (U1.38)
IDC_OC: pg3-Main (C42.2 R57.1), Pg2-Main_1 (U1.33)
PHU: pg3-Main (6 pins), Pg2-Main_1 (R9.2)
PHV: pg3-Main (6 pins), Pg2-Main_1 (R10.2)
PHW: pg3-Main (6 pins), Pg2-Main_1 (R11.2)
PWM_U_BOT: pg3-Main (R33.1), Pg2-Main_1 (U1.18)
PWM_U_TOP: pg3-Main (R32.1), Pg2-Main_1 (U1.16)
PWM_V_BOT: pg3-Main (R45.1), Pg2-Main_1 (U1.19)
PWM_V_TOP: pg3-Main (R42.1), Pg2-Main_1 (U1.24)
PWM_W_BOT: pg3-Main (R59.1), Pg2-Main_1 (U1.20)
PWM_W_TOP: pg3-Main (R56.1), Pg2-Main_1 (U1.32)
UART_RX: Pg1-Cover_1 (U9.2), Pg2-Main_1 (U1.15)
UART_TX: Pg1-Cover_1 (U9.3), Pg2-Main_1 (U1.6)

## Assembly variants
001: not fitted C49 R68 U10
